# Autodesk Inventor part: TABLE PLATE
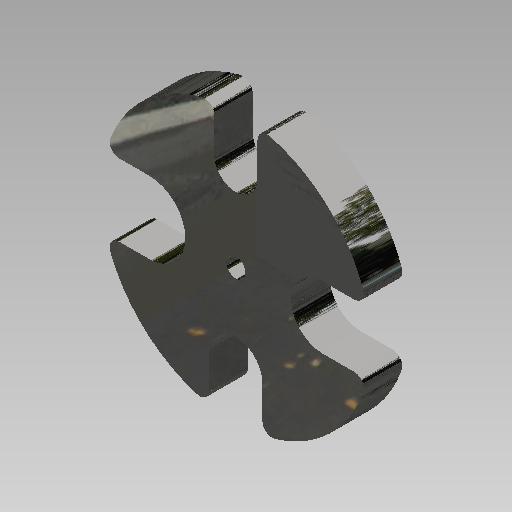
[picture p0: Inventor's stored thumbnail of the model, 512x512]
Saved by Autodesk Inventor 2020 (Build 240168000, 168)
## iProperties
Part Number: TABLE PLATE
Document SubType Name: Modeling
Created: 2003-11
Designer: Autodesk, Inc.
Manufacturer: Standard
Standards Organization: Custom
Mass: 436.046 g
Surface Area: 143.439 cm^2
Volume: 55.5473 cm^3
Density: 7.85 g/cm^3
Material: Steel, High Strength Low Alloy
Appearance: Steel - Polished
Control State: 0
Master: False
Checked Out: False
Shininess: 64.0
Length Units: 11272
Angle Units: 11279
Time Units: 11290
Mass Units: 11286
Length Display Precision: 3
Angle Display Precision: 2
Compacted: True
Density: 0.0
Volumn: 0.0
Area: 0.0
PropertySet Name: Model Information
Author: Autodesk, Inc.
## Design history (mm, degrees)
sketch "Sketch1"
  geometry: C1 r 44.45 at (0, 0); 1 further point
  constraints: 1 centre point, 1 coincident
  dimensions: "d0" = 88.9 diameter of C1
extrude "Extrusion1" new body sketch "Sketch1" distance "d1" = 12.7; taper "d2" = 0 deg
sketch "Sketch2"
  geometry: L1 (-7.137, 43.873)-(-7.137, 28.575); L2 (7.137, 43.873)-(7.137, 28.575); L3 (0, 0)-(0, 40.794); L4 (0, 0)-(-21.298, 0); L5 (-8.725, -28.575)-(-8.725, -43.585); L6 (8.725, -28.575)-(8.725, -43.585); L7 (-28.575, 11.9)-(-42.828, 11.9); L8 (-28.575, -11.9)-(-42.828, -11.9); L9 (28.575, 10.312)-(43.237, 10.312); L10 (28.575, -10.312)-(43.237, -10.312); A1 r 7.137 centre (0, 28.575) between (-7.137, 28.575) and (7.137, 28.575); A2 r 8.725 centre (0, -28.575) between (8.725, -28.575) and (-8.725, -28.575); A3 r 11.9 centre (-28.575, 0) between (-28.575, -11.9) and (-28.575, 11.9); A4 r 10.312 centre (28.575, 0) between (28.575, 10.312) and (28.575, -10.312); A5 r 28.575 centre (0, 0) between (0, 28.575) and (28.575, 0)
  constraints: 20 end point, 11 point on circle, 8 tangent, 5 centre point, 4 horizontal, 4 point on line, 3 parallel, 2 perpendicular, 1 coincident, 1 vertical, 9 other
  dimensions: "d3" = 14.2748 diameter of A1; "d4" = 28.575 distance of L3.start A1.centre; "d7" = 8.7249 radius of A2; "d8" = 28.575 distance of L3.start A2.centre; "d9" = 23.7998 diameter of A3; "d10" = 20.6248 diameter of A4
extrude "Extrusion2" cut sketch "Sketch2" extent not by distance; stored distance "d5" = 12.7; taper "d6" = 0 deg
fillet "Fillet1" dims "d11" = 3.175
sketch "Sketch3"
  geometry: C1 r 3.175 at (0, 0); 1 further point
  constraints: 1 centre point, 1 coincident
  dimensions: "d12" = 6.35 diameter of C1
extrude "Extrusion3" cut sketch "Sketch3" extent not by distance; stored distance "d13" = 12.7; taper "d14" = 0 deg
body "Solid1"
